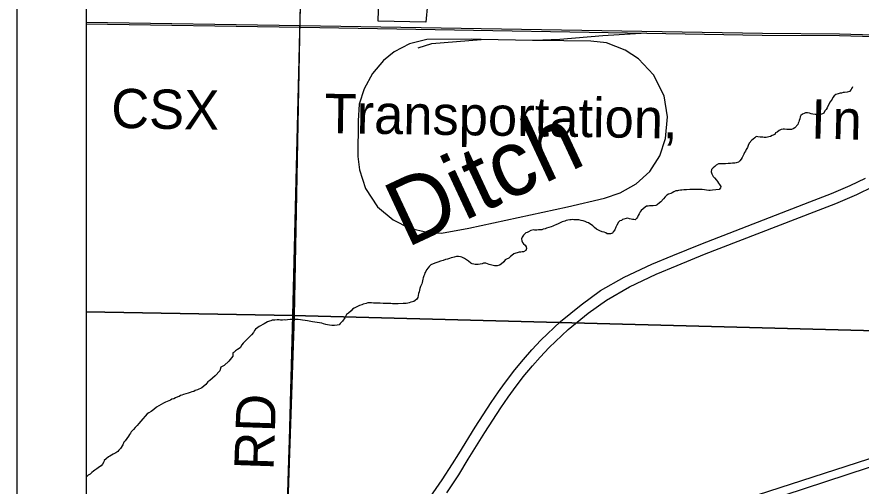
# Model space of a CAD drawing. Extents: x 0 to 34, y 0 to 22.
# Drawn here: x 2 to 3.218, y 17.233 to 17.91 of the extents above; entities that cross this region are included whole.
import ezdxf

# ---------------------------------------------------------------- set-up
doc = ezdxf.new("R2010")
doc.units = 0
for name, color, linetype in [('Default', 7, 'Continuous'), ('GM_X_County_Road', 7, 'Continuous'), ('GM_X_County_Road_Text', 7, 'Continuous'), ('GM_X_Minor_River', 7, 'Continuous'), ('GM_X_Minor_River_Text', 7, 'Continuous'), ('GM_X_Rail_Line', 7, 'Continuous'), ('GM_X_Rail_Line_Text', 7, 'Continuous'), ('GM_X_Section', 7, 'Continuous'), ('GM_X_Township_Road', 7, 'Continuous'), ('GM_X_US_Route', 7, 'Continuous'), ('SH_Data', 7, 'Continuous')]:
    doc.layers.add(name, color=color, linetype=linetype)

msp = doc.modelspace()

# ---------------------------------------------------------------- linework, layer by layer
at = {"layer": 'Default'}
for points in [[(2.1, 18.4972), (2.1, 17.4846), (2.3981, 17.4793), (2.4232, 18.4915)], [(2.1, 17.4846), (2.1, 16.4788), (2.3712, 16.4736), (2.3981, 17.4793)]]:
    msp.add_lwpolyline(points, close=True, dxfattribs=at)
msp.add_lwpolyline([(3.2732, 18.3207), (3.2023, 18.4583), (3.1913, 18.4721), (3.133, 18.4734), (3.1268, 18.0916), (3.1749, 18.0903), (3.1729, 17.965), (3.0789, 17.9675), (3.0808, 18.0863), (2.9154, 18.0918), (2.9116, 17.9727), (2.7589, 17.9762), (2.5972, 17.9807), (2.5899, 17.9025), (2.5214, 17.904), (2.5235, 17.9826), (2.4101, 17.9855), (2.4082, 17.9058), (2.4, 17.4786), (2.3849, 17.0266), (2.384, 16.9999), (4.2958, 17.6173)], dxfattribs=at)
at = {"layer": 'GM_X_County_Road'}
msp.add_lwpolyline([(2.3894, 17.1679), (2.3915, 17.2406), (2.393, 17.2866), (2.3941, 17.3226), (2.3956, 17.3717), (2.3968, 17.4078), (2.3976, 17.4314), (2.3983, 17.46), (2.3998, 17.5141), (2.4017, 17.5758), (2.4018, 17.5998), (2.4024, 17.6259), (2.4031, 17.6576), (2.4039, 17.6924), (2.4048, 17.7254), (2.4053, 17.749), (2.4057, 17.7683), (2.4078, 17.8702), (2.4085, 17.9053), (2.4095, 17.942)], dxfattribs=at)
at = {"layer": 'GM_X_Minor_River'}
for points in [[(3.2055, 17.809), (3.2046, 17.8067), (3.2046, 17.8071), (3.2038, 17.8052), (3.2015, 17.8026), (3.1981, 17.8015), (3.1942, 17.8009), (3.1923, 17.8009), (3.1897, 17.8002), (3.1878, 17.7999), (3.1847, 17.7988), (3.1816, 17.7978), (3.1793, 17.7963), (3.1773, 17.7937), (3.1761, 17.7915), (3.1734, 17.7877), (3.1702, 17.781), (3.169, 17.7787), (3.1674, 17.7765), (3.1658, 17.7743), (3.1642, 17.7713), (3.1623, 17.7702), (3.1596, 17.7691), (3.1562, 17.7688), (3.1539, 17.7692), (3.1517, 17.7693), (3.1483, 17.7698), (3.146, 17.7702), (3.1437, 17.771), (3.1407, 17.7715), (3.138, 17.7715), (3.1357, 17.7708), (3.1334, 17.7698), (3.1311, 17.7679), (3.1303, 17.766), (3.1295, 17.763), (3.1286, 17.7604), (3.1282, 17.7585), (3.127, 17.7566), (3.1266, 17.7547), (3.1223, 17.7499), (3.12, 17.7485), (3.1177, 17.7478), (3.115, 17.7478), (3.1128, 17.7475), (3.1109, 17.7476), (3.1074, 17.748), (3.1056, 17.7481), (3.1025, 17.7478), (3.0998, 17.7463), (3.0967, 17.7437), (3.0944, 17.7427), (3.0936, 17.7404), (3.0897, 17.739), (3.0871, 17.7375), (3.0851, 17.7368), (3.0832, 17.7365), (3.0809, 17.7362), (3.0783, 17.7362), (3.076, 17.7363), (3.0726, 17.7364), (3.0692, 17.7372), (3.0665, 17.7377), (3.0646, 17.7354), (3.0623, 17.7336), (3.0603, 17.7321), (3.0564, 17.7277), (3.0552, 17.7243), (3.054, 17.7217), (3.0524, 17.7187), (3.0512, 17.7164), (3.05, 17.7142), (3.0488, 17.7119), (3.0476, 17.7093), (3.0464, 17.707), (3.0452, 17.7048), (3.0432, 17.7022), (3.0413, 17.7007), (3.0379, 17.6993), (3.0356, 17.699), (3.0325, 17.699), (3.0295, 17.6987), (3.0261, 17.6984), (3.0223, 17.6982), (3.0177, 17.6983), (3.015, 17.6983), (3.0124, 17.698), (3.0089, 17.6962), (3.007, 17.6944), (3.0046, 17.6925), (3.0023, 17.6899), (3.0018, 17.6865), (3.0025, 17.6835), (3.0047, 17.68), (3.0065, 17.6777), (3.0095, 17.6745), (3.0106, 17.6726), (3.0121, 17.6703), (3.0139, 17.6684), (3.0154, 17.6653), (3.0153, 17.6634)], [(3.0153, 17.6634), (3.013, 17.6612), (3.0084, 17.6605), (3.0038, 17.6599), (3.0004, 17.6596), (2.9985, 17.6596), (2.9951, 17.6601), (2.9921, 17.6606), (2.9887, 17.661), (2.986, 17.6611), (2.9833, 17.6612), (2.9803, 17.6609), (2.9773, 17.6609), (2.9742, 17.661), (2.9708, 17.6611), (2.9659, 17.6608), (2.9621, 17.6606), (2.9594, 17.6603), (2.9575, 17.6599), (2.9548, 17.6596), (2.9529, 17.6593), (2.9506, 17.659), (2.9479, 17.6575), (2.9456, 17.6564), (2.9433, 17.6553), (2.9402, 17.6543), (2.9379, 17.6528), (2.9352, 17.6506), (2.9329, 17.6476), (2.9293, 17.6432), (2.927, 17.6417), (2.9239, 17.6391), (2.922, 17.638), (2.9182, 17.6374), (2.9144, 17.6375), (2.9125, 17.6375), (2.9106, 17.6372), (2.9083, 17.6369), (2.9064, 17.6358), (2.9009, 17.631), (2.8993, 17.6287), (2.8978, 17.6261), (2.8966, 17.6235), (2.8954, 17.6212), (2.8942, 17.619), (2.8922, 17.6175), (2.8903, 17.6176), (2.8881, 17.618), (2.8862, 17.6184), (2.8839, 17.6189), (2.8813, 17.6197), (2.879, 17.6194), (2.8759, 17.6183), (2.874, 17.6176), (2.8721, 17.6165), (2.8701, 17.6158), (2.8678, 17.614), (2.8658, 17.6095), (2.8642, 17.6065), (2.8626, 17.6031), (2.8603, 17.6001), (2.8591, 17.5982), (2.8564, 17.5972), (2.8545, 17.5972), (2.8515, 17.5973), (2.8496, 17.5985), (2.8473, 17.5993), (2.8443, 17.6001), (2.8413, 17.6014), (2.8364, 17.6038), (2.8334, 17.6061), (2.8308, 17.6085), (2.829, 17.61), (2.8267, 17.6116), (2.8245, 17.6132), (2.8226, 17.6136), (2.82, 17.6148), (2.817, 17.616), (2.8143, 17.6165), (2.8109, 17.6173), (2.8087, 17.6174), (2.8064, 17.6174), (2.8037, 17.6175), (2.8014, 17.6176), (2.7995, 17.6172), (2.7976, 17.6173), (2.795, 17.6166), (2.7927, 17.6163), (2.7908, 17.6156), (2.7888, 17.6149), (2.7865, 17.6142), (2.7839, 17.6131), (2.7808, 17.6116), (2.7777, 17.6102), (2.7754, 17.6091), (2.7731, 17.608), (2.7708, 17.6073), (2.7677, 17.6063), (2.7643, 17.6052), (2.7624, 17.6045), (2.7593, 17.6038)], [(2.7593, 17.6038), (2.7574, 17.6031), (2.7551, 17.6028), (2.7524, 17.6029), (2.7502, 17.6025), (2.7475, 17.6026), (2.7456, 17.6027), (2.7414, 17.602), (2.7383, 17.6002), (2.736, 17.5991), (2.7341, 17.5984), (2.731, 17.5954), (2.729, 17.5925), (2.7282, 17.5898), (2.7285, 17.5868), (2.7296, 17.5848), (2.7311, 17.5829), (2.7333, 17.5806), (2.7347, 17.5786), (2.7351, 17.576), (2.7342, 17.573), (2.7308, 17.5711), (2.7289, 17.5712), (2.727, 17.5709), (2.7247, 17.5705), (2.722, 17.5698), (2.7197, 17.5691), (2.717, 17.5681), (2.7139, 17.5659), (2.712, 17.5644), (2.7096, 17.5622), (2.7066, 17.5607), (2.7046, 17.5597), (2.7027, 17.5567), (2.6988, 17.5533), (2.6961, 17.5519), (2.693, 17.5512), (2.6911, 17.5509), (2.6892, 17.5509), (2.6873, 17.5514), (2.6851, 17.5518), (2.6832, 17.5522), (2.6813, 17.5527), (2.679, 17.5539), (2.6768, 17.5547), (2.6734, 17.5548), (2.6711, 17.5541), (2.6684, 17.5534), (2.6657, 17.5531), (2.6631, 17.5527), (2.6612, 17.5528), (2.6593, 17.5532), (2.657, 17.554), (2.6551, 17.5548), (2.6518, 17.5576), (2.6488, 17.5596), (2.6458, 17.5615), (2.6439, 17.5627), (2.6421, 17.5635), (2.6402, 17.564), (2.6371, 17.5644), (2.6345, 17.5645), (2.631, 17.5634), (2.6291, 17.5631), (2.6268, 17.5624), (2.6242, 17.5617), (2.6211, 17.5607), (2.6184, 17.56), (2.615, 17.5589), (2.6112, 17.5579), (2.6073, 17.5565), (2.6031, 17.555), (2.5973, 17.5525), (2.595, 17.5499), (2.5934, 17.5481), (2.5911, 17.5451), (2.5899, 17.5428), (2.5887, 17.541), (2.5879, 17.5383), (2.5871, 17.5365), (2.5862, 17.5338), (2.5858, 17.5316), (2.585, 17.5293), (2.5846, 17.527), (2.5841, 17.5251), (2.5833, 17.5233), (2.5821, 17.521), (2.5813, 17.5184), (2.5809, 17.5161), (2.5804, 17.5135), (2.5796, 17.5112), (2.5791, 17.5082), (2.5783, 17.5055), (2.5771, 17.5029), (2.5748, 17.5011), (2.5725, 17.4996), (2.5706, 17.4989), (2.5686, 17.4986), (2.566, 17.4975), (2.5641, 17.4972), (2.5618, 17.4968)], [(2.5618, 17.4968), (2.5595, 17.4969), (2.5572, 17.4966), (2.5503, 17.496), (2.5477, 17.4961), (2.5443, 17.4962), (2.542, 17.4962), (2.5393, 17.4967), (2.5363, 17.4967), (2.534, 17.4968), (2.5314, 17.4969), (2.5287, 17.4969), (2.5242, 17.4971), (2.5219, 17.4971), (2.52, 17.4972), (2.5173, 17.4972), (2.5143, 17.4973), (2.5116, 17.4978), (2.5094, 17.4978), (2.5063, 17.4975), (2.504, 17.4968), (2.4998, 17.4958), (2.4975, 17.4947), (2.4944, 17.4936), (2.4914, 17.4922), (2.4887, 17.4911), (2.4864, 17.49), (2.4841, 17.4886), (2.4821, 17.486), (2.4786, 17.4826), (2.4755, 17.4808), (2.4747, 17.479), (2.4731, 17.476), (2.47, 17.4711), (2.4665, 17.4678), (2.4649, 17.4659), (2.4622, 17.4652), (2.4584, 17.4649), (2.4542, 17.465), (2.4508, 17.4655), (2.4482, 17.466), (2.4459, 17.4664), (2.4425, 17.4672), (2.4399, 17.4681), (2.4365, 17.4689), (2.4331, 17.4694), (2.4297, 17.4699), (2.4266, 17.4703), (2.424, 17.4708), (2.4217, 17.4712), (2.4191, 17.4716), (2.416, 17.4721), (2.4123, 17.4726), (2.4092, 17.473), (2.4058, 17.4735), (2.4028, 17.4736), (2.4009, 17.4736), (2.3944, 17.4734), (2.3906, 17.4731), (2.3876, 17.4728), (2.3857, 17.4729), (2.383, 17.4726), (2.3803, 17.4726), (2.3785, 17.4731), (2.3754, 17.4731), (2.3724, 17.4728), (2.3682, 17.4726), (2.3663, 17.4719), (2.3644, 17.4711), (2.3617, 17.4701), (2.3594, 17.469), (2.3567, 17.4675), (2.3497, 17.4635), (2.3474, 17.4621), (2.3443, 17.4595), (2.3427, 17.4576), (2.3412, 17.455), (2.3384, 17.4517), (2.3357, 17.4487), (2.333, 17.4461), (2.3306, 17.4439), (2.3291, 17.442), (2.3267, 17.4395), (2.3244, 17.4369), (2.322, 17.4327), (2.3181, 17.4302), (2.3154, 17.4283), (2.3135, 17.4265), (2.3115, 17.4254), (2.3114, 17.4209), (2.3059, 17.4134), (2.2989, 17.4071), (2.2943, 17.405), (2.2927, 17.3997), (2.286, 17.3923), (2.2783, 17.3856), (2.2756, 17.3838), (2.2724, 17.3797), (2.2666, 17.3753), (2.2608, 17.372), (2.2574, 17.371)], [(2.2574, 17.371), (2.2551, 17.3699), (2.2524, 17.3692), (2.2501, 17.3685), (2.247, 17.3674), (2.2436, 17.3664), (2.2405, 17.3653), (2.2382, 17.3646), (2.2363, 17.3639), (2.234, 17.3628), (2.2321, 17.3621), (2.229, 17.3607), (2.2263, 17.3592), (2.2236, 17.3585), (2.2217, 17.3574), (2.2194, 17.3564), (2.2167, 17.3553), (2.2144, 17.3542), (2.2117, 17.3528), (2.2083, 17.351), (2.2048, 17.3491), (2.2013, 17.347), (2.1978, 17.3436), (2.1936, 17.3411), (2.1905, 17.3389), (2.1878, 17.3374), (2.1851, 17.3341), (2.1819, 17.3304), (2.1788, 17.327), (2.1761, 17.3237), (2.1733, 17.3207), (2.1706, 17.3177), (2.1682, 17.3148), (2.1651, 17.3118), (2.1639, 17.3099), (2.1624, 17.3077), (2.1608, 17.3055), (2.1588, 17.3021), (2.1561, 17.2987), (2.1541, 17.2969), (2.1529, 17.2931), (2.1493, 17.2875), (2.147, 17.2853), (2.1458, 17.2834), (2.1427, 17.2812), (2.1389, 17.2794), (2.1365, 17.278), (2.1342, 17.2765), (2.1323, 17.2754), (2.1288, 17.2729), (2.1261, 17.2703), (2.1253, 17.2684), (2.1237, 17.265), (2.1214, 17.2628), (2.1194, 17.2613), (2.1171, 17.2595), (2.1152, 17.2584), (2.1124, 17.2562), (2.1105, 17.2547), (2.1082, 17.2529), (2.1055, 17.2507), (2.1028, 17.2492), (2.1008, 17.2474), (2.1, 17.2467)]]:
    msp.add_lwpolyline(points, dxfattribs=at)
at = {"layer": 'GM_X_Rail_Line'}
msp.add_line((2.7439, 17.8761), (2.6697, 17.8774), dxfattribs=at)
for points in [[(2.1, 17.9025), (2.4093, 17.8974), (3.0756, 17.8863), (3.1869, 17.8856), (3.2694, 17.883)], [(2.1, 17.9), (2.4093, 17.8949), (3.0755, 17.8838), (3.1869, 17.8831), (3.2694, 17.8805)], [(2.9085, 17.8866), (2.8456, 17.8826), (2.7834, 17.8773), (2.7462, 17.876), (2.7439, 17.8761)], [(2.6697, 17.8774), (2.6555, 17.8777), (2.5916, 17.8773), (2.5663, 17.8713), (2.5441, 17.8598), (2.5291, 17.8471), (2.5133, 17.8284), (2.501, 17.8062), (2.4938, 17.784), (2.4926, 17.7601), (2.4917, 17.7088), (2.4942, 17.6892), (2.503, 17.6623), (2.5205, 17.636), (2.5429, 17.6175), (2.5665, 17.6054), (2.592, 17.5994), (2.6128, 17.5982), (2.652, 17.6052), (2.7945, 17.6362), (2.8479, 17.6486), (2.8705, 17.6562), (2.8937, 17.6693), (2.9134, 17.6872), (2.9278, 17.7098), (2.936, 17.7347), (2.9389, 17.7659), (2.9338, 17.7961), (2.9186, 17.8263), (2.8968, 17.8493), (2.8775, 17.8619), (2.8508, 17.8724), (2.8282, 17.875), (2.7889, 17.8752), (2.7439, 17.8761)], [(2.5789, 17.8654), (2.5988, 17.8715), (2.6697, 17.8774)], [(2.1, 16.8913), (2.3829, 16.983), (4.2841, 17.6061)]]:
    msp.add_lwpolyline(points, dxfattribs=at)
at = {"layer": 'GM_X_Section'}
for points in [[(3.4283, 18.4755), (3.4048, 17.4531), (2.3981, 17.4793), (2.4232, 18.4915)], [(2.3981, 17.4793), (3.4048, 17.4531), (3.3743, 16.4525), (2.3859, 16.4729), (2.3712, 16.4736)]]:
    msp.add_lwpolyline(points, close=True, dxfattribs=at)
at = {"layer": 'GM_X_Township_Road'}
msp.add_lwpolyline([(3.3048, 18.313), (3.1897, 18.5004), (3.1172, 18.5567), (3.0436, 18.5785), (2.9471, 18.583), (2.8689, 18.5622), (2.7827, 18.53), (2.7034, 18.538), (2.6091, 18.5782), (2.5458, 18.631), (2.4813, 18.7), (2.402, 18.7551), (2.324, 18.7883), (2.27, 18.7918), (2.2228, 18.7618), (2.2102, 18.7216), (2.2161, 18.5687), (2.2104, 18.5353), (2.1828, 18.4744), (2.1346, 18.4226), (2.1, 18.4074), (2.1, 14.1)], dxfattribs=at)
at = {"layer": 'GM_X_US_Route'}
for points in [[(2.5961, 17.2176), (2.6137, 17.2422), (2.6287, 17.2654), (2.6374, 17.2799), (2.6614, 17.3182), (2.6843, 17.3537), (2.695, 17.3693), (2.7035, 17.3812), (2.7185, 17.4012), (2.7308, 17.4159), (2.743, 17.43), (2.7561, 17.444), (2.7841, 17.4708), (2.8139, 17.4949), (2.8422, 17.5156), (2.8762, 17.5348), (2.9162, 17.5532), (2.9466, 17.5661), (2.9867, 17.582), (3.1439, 17.6432), (3.1751, 17.6555), (3.2024, 17.6667), (3.2244, 17.6774)], [(2.6203, 17.2238), (2.6376, 17.2498), (2.6512, 17.2722), (2.6752, 17.3106), (2.6981, 17.3463), (2.7088, 17.3614), (2.7167, 17.3724), (2.7305, 17.3909), (2.7439, 17.4066), (2.7551, 17.4193), (2.7678, 17.433), (2.7956, 17.4593), (2.824, 17.4828), (2.8509, 17.5014), (2.8838, 17.5205), (2.9224, 17.5388), (2.9525, 17.5515), (2.992, 17.5677), (3.1501, 17.6287), (3.1817, 17.6407), (3.2119, 17.6537), (3.2355, 17.6654)]]:
    msp.add_lwpolyline(points, dxfattribs=at)
at = {"layer": 'SH_Data'}
for p, q in [((2, 21), (2, 14)), ((2.1, 20.9), (2.1, 14.1))]:
    msp.add_line(p, q, dxfattribs=at)

# ---------------------------------------------------------------- texts
at = {"layer": 'GM_X_County_Road_Text'}
msp.add_text('RD', height=0.05682, rotation=88.0373, dxfattribs=at).set_placement((2.3703, 17.2557))
at = {"layer": 'GM_X_Minor_River_Text'}
msp.add_text('Ditch', height=0.09474, rotation=25.0385, dxfattribs=at).set_placement((2.5622, 17.5765))
at = {"layer": 'GM_X_Rail_Line_Text'}
for s, height, rotation, p in [('CSX', 0.05663, 358.9397, (2.1357, 17.75)), ('Transportation,', 0.056629, 359.0895, (2.4436, 17.7426)), ('I', 0.0566, 358.4107, (3.1452, 17.7348)), ('n', 0.0566, 358.567, (3.1762, 17.7339))]:
    msp.add_text(s, height=height, rotation=rotation, dxfattribs=at).set_placement(p)

doc.saveas('drawing.dxf')
